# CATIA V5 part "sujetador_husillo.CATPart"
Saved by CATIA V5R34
Part number: sujetador_husillo
Bounding box of the stored display mesh (mm): x -27.5 to 27.5, y -41.721 to 31, z -25 to 60.531
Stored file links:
  C:\Users\Apolinar\Desktop\cnc\sujetador_husillo.CATPart
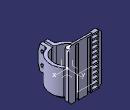
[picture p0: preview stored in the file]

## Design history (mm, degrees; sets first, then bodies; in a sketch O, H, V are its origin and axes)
AxisSystem1: origin (0, 0, 0), X (1, 0, 0), Y (0, 1, 0), Z (0, 0, 1)
Body1 (main body)
  Sketch1 on XY plane of AxisSystem1, origin (0, 0, 0), H (1, 0, 0), V (0, 1, 0)
    arc A1 centre (0, 0) radius 22.5 from (0, 22.5) to (-1.5, -22.4499) ccw
    arc A2 centre (0, 0) radius 27.5 from (0, 27.5) to (-6.5, -26.7208) ccw
    point P1 (-1.5, -22.4499)
    line L1 (-1.5, -22.4499) -> (-1.5, -28.4355)
    point P2 (-1.5, -28.4355)
    point P3 (-6.5, -26.7208)
    line L2 (-6.5, -26.7208) -> (-6.5, -41.7208)
    point P4 (-6.5, -41.7208)
    line L3 (-6.5, -41.7208) -> (-1.5, -41.7208)
    point P5 (-1.5, -41.7208)
    line L4 (-1.5, -41.7208) -> (-1.5, -28.4355)
    axis line L5 (0, 34.1099) -> (0, -44.3897)
    point P6 (0, 34.1099)
    point P7 (0, -44.3897)
    point P8 (0, 22.5)
    point P9 (0, 27.5)
    point P10 (1.5, -22.4499)
    point P11 (1.5, -28.4355)
    point P12 (6.5, -26.7208)
    point P13 (6.5, -41.7208)
    point P14 (1.5, -41.7208)
    point P15 (0, -44.3897)
    line L6 (1.5, -22.4499) -> (1.5, -28.4355)
    line L7 (6.5, -26.7208) -> (6.5, -41.7208)
    line L8 (6.5, -41.7208) -> (1.5, -41.7208)
    line L9 (1.5, -41.7208) -> (1.5, -28.4355)
    point P16 (0, 27.5)
    arc A3 centre (0, 0) radius 27.5 from (0, 27.5) to (6.5, -26.7208) cw
    point P18 (0, 22.5)
    arc A4 centre (0, 0) radius 22.5 from (0, 22.5) to (1.5, -22.4499) cw
    distance A2 A1 = 5
    radius A1 = 22.5
    length L2 = 15
    length L3 = 5
    distance L4 V = 1.5
    vertical: L1 V, L2 V, L4 V, L5 V
    coincidence: P5 L1, P6 V, L5 P8, L5 P9
    horizontal: L3 H
    symmetry: P1 P10 L5, P2 P11 L5, P3 P12 L5, P4 P13 L5, P5 P14 L5, P7 P15 L5, L1 L6 L5, L2 L7 L5, L3 L8 L5, L4 L9 L5, P9 P16 L5, A2 A3 L5, P8 P18 L5, A1 A4 L5
  Pad1: profile Sketch1, direction (0, 0, 1), length 20, mirrored extent
  Sketch2 on face of Pad1 from Sketch1.L7, origin (6.5, 0, 0), H (0, 1, 0), V (0, 0, 1)
    point P1 (-34.2208, 10)
    point P2 (-34.2208, 12.7)
    construction circle A1 centre (-34.2208, 10) radius 3.1177
    construction circle A2 centre (-34.2208, 10) radius 2.7
    point P3 (-32.6619, 12.7)
    point P4 (-35.7796, 12.7)
    point P5 (-37.3385, 10)
    point P6 (-35.7796, 7.3)
    point P7 (-32.6619, 7.3)
    point P8 (-31.1031, 10)
    line L1 (-32.6619, 12.7) -> (-35.7796, 12.7)
    line L2 (-35.7796, 12.7) -> (-37.3385, 10)
    line L3 (-37.3385, 10) -> (-35.7796, 7.3)
    line L4 (-35.7796, 7.3) -> (-32.6619, 7.3)
    line L5 (-32.6619, 7.3) -> (-31.1031, 10)
    line L6 (-31.1031, 10) -> (-32.6619, 12.7)
    construction line L7 (-34.2208, 10) -> (-34.2208, 12.7)
    reference projected line E1 (-41.7208, -20) -> (-41.7208, 20) from edge [face of Pad1 from Sketch1.L7 | face of Pad1 from Sketch1.L8]
    reference projected line E2 (-26.7208, -20) -> (-26.7208, 20) from edge [face of Pad1 from Sketch1.A3 | face of Pad1 from Sketch1.L7]
    reference projected line E3 (-41.7208, -20) -> (-41.7208, 20) from edge [face of Pad1 from Sketch1.L3 | face of Pad1 from Sketch1.L2]
    point P10 (-34.2208, -12.7)
    construction circle A3 centre (-34.2208, -10) radius 3.1177
    construction circle A4 centre (-34.2208, -10) radius 2.7
    point P11 (-32.6619, -12.7)
    point P12 (-35.7796, -12.7)
    point P13 (-37.3385, -10)
    point P14 (-35.7796, -7.3)
    point P15 (-32.6619, -7.3)
    point P16 (-31.1031, -10)
    construction line L8 (-34.2208, -10) -> (-34.2208, -12.7)
    line L9 (-32.6619, -12.7) -> (-35.7796, -12.7)
    line L10 (-35.7796, -12.7) -> (-37.3385, -10)
    line L11 (-37.3385, -10) -> (-35.7796, -7.3)
    line L12 (-35.7796, -7.3) -> (-32.6619, -7.3)
    line L13 (-32.6619, -7.3) -> (-31.1031, -10)
    line L14 (-31.1031, -10) -> (-32.6619, -12.7)
    distance L4 L1 = 5.4
    distance P1 H = 10
    distance E1 E2 = 15 (reference)
    distance E3 P1 = 7.5
    coincidence: A1 P3, A1 P4, A1 P5, A1 P6, A1 P7, A1 P8
    tangency: A2 L1, A2 L2, A2 L3, A2 L4, A2 L5, A2 L6
    midpoint: P2 L1
    vertical: L7 V
    symmetry: P2 P10 H, A1 A3 H, A2 A4 H, P3 P11 H, P4 P12 H, P5 P13 H, P6 P14 H, P7 P15 H, P8 P16 H, L7 L8 H, L1 L9 H, L2 L10 H, L3 L11 H, L4 L12 H, L5 L13 H, L6 L14 H
  Pocket1: profile Sketch2, direction (-1, 0, 0), length 3
  Sketch3 on end face of Pocket1, origin (3.5, 0, 0), H (0, 1, 0), V (0, 0, 1)
    circle A1 centre (-34.2208, 10) radius 1.75
    point P1 (-34.2208, 10)
    reference projected line E1 (-41.7208, -20) -> (-41.7208, 20) from edge [face of Pad1 from Sketch1.L7 | face of Pad1 from Sketch1.L8]
    reference projected line E2 (-41.7208, 20) -> (-26.7208, 20) from edge [face of Pad1 from Sketch1.L7 | end face of Pad1]
    circle A2 centre (-34.2208, -10) radius 1.75
    radius A1 = 1.75
    distance P1 E1 = 7.5
    distance P1 E2 = 10
    symmetry: A1 A2 H
  Pocket2: profile Sketch3, direction (-1, 0, 0), through (limit type 3)
  Sketch4 on start face of Pad1, origin (0, 0, -20), H (1, 0, 0), V (0, -1, 0)
    arc A1 centre (0, 0) radius 9.25 from (-1.5, 9.1276) to (1.5, 9.1276) ccw
    arc A2 centre (0, 0) radius 27.5 from (-1.5, 27.4591) to (1.5, 27.4591) ccw
    reference projected arc E1 centre (0, 0) radius 27.5 from (0, -27.5) to (6.5, 26.7208) ccw from edge [start face of Pad1 | face of Pad1 from Sketch1.A3]
    line L1 (-1.5, 9.1276) -> (-1.5, 27.4591)
    line L2 (1.5, 9.1276) -> (1.5, 27.4591)
    reference projected line E2 (-1.5, 28.4355) -> (-1.5, 22.4499) from edge [start face of Pad1 | face of Pad1 from Sketch1.L1]
    reference projected line E3 (1.5, 22.4499) -> (1.5, 28.4355) from edge [start face of Pad1 | face of Pad1 from Sketch1.L6]
    circle A3 centre (-14.25, 0) radius 2.25
    point P5 (-14.25, 0)
    reference projected arc E4 centre (0, 0) radius 22.5 from (-1.5, 22.4499) to (0, -22.5) ccw from edge [start face of Pad1 | face of Pad1 from Sketch1.A1]
    circle A4 centre (14.25, 0) radius 2.25
    radius A1 = 9.25
    radius A3 = 2.25
    distance A3 E4 = 6
    coincidence: E1 A2, L1 E2, L2 E3, P5 H
    vertical: L1 V, L2 V
    symmetry: A3 A4 V
  Pad2: profile Sketch4, direction (0, 0, -1), length 5
  Chamfer1: length 3, angle 45, on edge [face of Pad2 | end face of Pad2]
  Fillet1: radius 3, on edge [start face of Pad2 | face of Pad1 from Sketch1.A1]
  Plane1: type Offset, RefPlane ZX plane of AxisSystem1, Offset 30
  Sketch5 on Plane1, origin (0, 30, 0), H (-1, 0, 0), V (0, 0, 1)
    point P1 (0, 17.5)
    line L1 (27.5, 60) -> (27.5, -22)
    line L2 (24.5, -25) -> (-24.5, -25)
    line L3 (-27.5, -22) -> (-27.5, 60)
    line L4 (-27.5, 60) -> (27.5, 60)
    reference projected line E1 (24.5, -25) -> (-24.5, -25) from edge [face of Chamfer1 | end face of Pad2]
    point P5 (27.5, -22)
    point P7 (-27.5, -22)
    reference projected line E2 (27.5, -22) -> (-27.5, -22) from edge [face of Pad2 | face of Chamfer1]
    line L5 (-27.5, -22) -> (-27.5, -25)
    point P8 (-27.5, -25)
    line L6 (-27.5, -25) -> (-24.5, -25)
    line L7 (24.5, -25) -> (27.5, -25)
    point P9 (27.5, -25)
    line L8 (27.5, -25) -> (27.5, -22)
    distance V L1 = 27.5
    distance L4 L2 = 85
    coincidence: P1 V, E1 L2, P5 E2, E2 P7, P8 L2, P9 L1
    vertical: L1 V, L3 V, L5 V, L8 V
    horizontal: L2 H, L4 H, L6 H, L7 H
    equidistance: L1 L3 P1, L2 L4 P1
  Pad3: profile Sketch5, direction (0, -1, 0), length 6
  DatumCurve1
  Sketch6 on start face of Pad3, origin (0, 30, 0), H (-1, 0, 0), V (0, 0, 1)
    point P1 (16.5, 17.5)
    line L1 (21.5, 60) -> (21.5, -25)
    line L2 (21.5, -25) -> (11.5, -25)
    line L3 (11.5, -25) -> (11.5, 60)
    line L4 (11.5, 60) -> (21.5, 60)
    reference projected line E1 (27.5, 60) -> (-27.5, 60) from edge [face of Pad3 from Sketch5.L4 | start face of Pad3]
    reference projected line E2 (-24.5, -25) -> (24.5, -25) from edge [face of Pad3 from Sketch5.L2 | start face of Pad3]
    reference projected line E3 (21.5, 55) -> (21.5, 60) from edge of DatumCurve1
    distance L1 L3 = 10
    vertical: L1 V, L3 V
    horizontal: L2 H, L4 H
    equidistance: L1 L3 P1, L2 L4 P1
    coincidence: L4 E1, E2 L2
    tangency: L1 E3
  Pocket3: profile Sketch6, direction (0, -1, 0), length 4
  Sketch7 on face of Pocket3 from Sketch6.L3, origin (-11.5, 0, 0), H (0, -1, 0), V (0, 0, 1)
    point P1 (-26, -25)
    line L1 (-26, -25) -> (-31, -23.6603)
    line L2 (-31, -23.6603) -> (-31, -21.3397)
    line L3 (-31, -21.3397) -> (-26, -20)
    line L4 (-26, -20) -> (-26, -25)
    reference projected line E1 (-26, 60) -> (-26, -25) from edge [end face of Pocket3 | face of Pocket3 from Sketch6.L3]
    reference projected line E2 (-30, -25) -> (-26, -25) from edge [face of Pad3 | face of Pocket3 from Sketch6.L3]
    axis line L5 (-31, -22.5) -> (-26, -22.5)
    point P5 (-31, -22.5)
    point P6 (-26, -22.5)
    construction line L6 (-31, -15.179) -> (-26, -15.179)
    line L7 (-26, -17.679) -> (-31, -16.3393)
    line L8 (-31, -16.3393) -> (-31, -14.0187)
    line L9 (-31, -14.0187) -> (-26, -12.679)
    line L10 (-26, -12.679) -> (-26, -17.679)
    construction line L11 (-31, -7.858) -> (-26, -7.858)
    line L12 (-26, -10.358) -> (-31, -9.0183)
    line L13 (-31, -9.0183) -> (-31, -6.6977)
    line L14 (-31, -6.6977) -> (-26, -5.358)
    line L15 (-26, -5.358) -> (-26, -10.358)
    construction line L16 (-31, -0.537) -> (-26, -0.537)
    line L17 (-26, -3.037) -> (-31, -1.6973)
    line L18 (-31, -1.6973) -> (-31, 0.6233)
    line L19 (-31, 0.6233) -> (-26, 1.963)
    line L20 (-26, 1.963) -> (-26, -3.037)
    construction line L21 (-31, 6.784) -> (-26, 6.784)
    line L22 (-26, 4.284) -> (-31, 5.6237)
    line L23 (-31, 5.6237) -> (-31, 7.9443)
    line L24 (-31, 7.9443) -> (-26, 9.284)
    line L25 (-26, 9.284) -> (-26, 4.284)
    construction line L26 (-31, 14.105) -> (-26, 14.105)
    line L27 (-26, 11.605) -> (-31, 12.9447)
    line L28 (-31, 12.9447) -> (-31, 15.2653)
    line L29 (-31, 15.2653) -> (-26, 16.605)
    line L30 (-26, 16.605) -> (-26, 11.605)
    construction line L31 (-31, 21.426) -> (-26, 21.426)
    line L32 (-26, 18.926) -> (-31, 20.2657)
    line L33 (-31, 20.2657) -> (-31, 22.5863)
    line L34 (-31, 22.5863) -> (-26, 23.926)
    line L35 (-26, 23.926) -> (-26, 18.926)
    construction line L36 (-31, 28.747) -> (-26, 28.747)
    line L37 (-26, 26.247) -> (-31, 27.5867)
    line L38 (-31, 27.5867) -> (-31, 29.9073)
    line L39 (-31, 29.9073) -> (-26, 31.247)
    line L40 (-26, 31.247) -> (-26, 26.247)
    construction line L41 (-31, 36.068) -> (-26, 36.068)
    line L42 (-26, 33.568) -> (-31, 34.9077)
    line L43 (-31, 34.9077) -> (-31, 37.2283)
    line L44 (-31, 37.2283) -> (-26, 38.568)
    line L45 (-26, 38.568) -> (-26, 33.568)
    construction line L46 (-31, 43.389) -> (-26, 43.389)
    line L47 (-26, 40.889) -> (-31, 42.2287)
    line L48 (-31, 42.2287) -> (-31, 44.5493)
    line L49 (-31, 44.5493) -> (-26, 45.889)
    line L50 (-26, 45.889) -> (-26, 40.889)
    construction line L51 (-31, 50.71) -> (-26, 50.71)
    line L52 (-26, 48.21) -> (-31, 49.5497)
    line L53 (-31, 49.5497) -> (-31, 51.8703)
    line L54 (-31, 51.8703) -> (-26, 53.21)
    line L55 (-26, 53.21) -> (-26, 48.21)
    construction line L56 (-31, 58.031) -> (-26, 58.031)
    line L57 (-26, 55.531) -> (-31, 56.8707)
    line L58 (-31, 56.8707) -> (-31, 59.1913)
    line L59 (-31, 59.1913) -> (-26, 60.531)
    line L60 (-26, 60.531) -> (-26, 55.531)
    angle L1 L4 = 75
    distance L2 L4 = 5
    length L4 = 5
    length L2 = 2.3205 (reference)
    vertical: L2 V, L4 V
    coincidence: E1 L4, P1 E2
    horizontal: L5 H
    midpoint: P5 L2, P6 L4
  Pad4: profile Sketch7, direction (-1, 0, 0), length 10
  DatumCurve2 to DatumCurve12
  Sketch8 on face of Pad3 from Sketch5.L4, origin (0, 0, 60), H (1, 0, 0), V (0, 1, 0)
    line L1 (-9.0986, 30) -> (-11.2427, 25.7117)
    line L2 (-11.2427, 25.7117) -> (-1.7573, 25.7117)
    line L3 (-1.7573, 25.7117) -> (-3.9014, 30)
    line L4 (-3.9014, 30) -> (-9.0986, 30)
    reference projected line E1 (-27.5, 30) -> (27.5, 30) from edge [face of Pad3 from Sketch5.L4 | start face of Pad3]
    reference projected line E2 (-9, 29.8617) -> (-11, 25.8617) from edge of DatumCurve2
    reference projected line E3 (-2, 25.8617) -> (-4, 29.8617) from edge of DatumCurve3
    reference projected line E4 (-2, 25.8617) -> (-4, 29.8617) from edge of DatumCurve4
    reference projected line E5 (-9, 29.8617) -> (-11, 25.8617) from edge of DatumCurve5
    reference projected line E6 (-11, 25.8617) -> (-2, 25.8617) from edge of DatumCurve6
    line L5 (11.1514, 30) -> (16.3486, 30)
    line L6 (16.3486, 30) -> (18.4927, 25.7117)
    line L7 (18.4927, 25.7117) -> (9.0073, 25.7117)
    line L8 (9.0073, 25.7117) -> (11.1514, 30)
    reference projected line E7 (11.25, 29.8617) -> (9.25, 25.8617) from edge of DatumCurve7
    reference projected line E8 (18.25, 25.8617) -> (16.25, 29.8617) from edge of DatumCurve8
    reference projected line E9 (18.25, 25.8617) -> (16.25, 29.8617) from edge of DatumCurve9
    reference projected line E10 (11.25, 29.8617) -> (9.25, 25.8617) from edge of DatumCurve10
    reference projected line E11 (9.25, 25.8617) -> (18.25, 25.8617) from edge of DatumCurve12
    distance E4 L3 = 0.15
    distance L1 E5 = 0.15
    distance E6 L2 = 0.15
    distance L6 E9 = 0.15
    distance L8 E10 = 0.15
    distance L7 E11 = 0.15
    horizontal: L2 H, L5 H, L7 H
    coincidence: E1 L4, L5 E1
    parallelism: L1 E2, E3 L3, L8 E7, E8 L6
  Pocket4: profile Sketch8, direction (0, 0, -1), through (limit type 6), opposite side length -3
  Fillet2: radius 5, on edge [face of Pad2 | end face of Pad3]; edge [end face of Pad3 | face of Pad2]
  Chamfer2: length 3, angle 75, on edge [face of Pad1 from Sketch1.L8 | end face of Pad1]; edge [face of Pad1 from Sketch1.L3 | end face of Pad1]; edge [start face of Pad1 | face of Pad1 from Sketch1.L8]; edge [start face of Pad1 | face of Pad1 from Sketch1.L3]
  Fillet3: radius 5, on edge [face of Pad1 from Sketch1.L2 | face of Pad2]; edge [face of Pad2 | face of Pad1 from Sketch1.L7]
  Fillet4: radius 3, on edge [face of Pad1 from Sketch1.A1 | face of Pad1]; edge [face of Pad1 | face of Pad1 from Sketch1.A4]
  Chamfer3: length 5, angle 45, on edge [face of Pad3 from Sketch5.L5 | face of Pad3 from Sketch5.L6]; edge [face of Pad3 from Sketch5.L7 | face of Pad3 from Sketch5.L8]; edge [face of Pad3 from Sketch5.L1 | face of Pad3 from Sketch5.L4]; edge [face of Pad3 from Sketch5.L4 | face of Pad3 from Sketch5.L3]
  Chamfer4: length 3, angle 45, on edge [end face of Pad3 | face of Pad3 from Sketch5.L4]
  Fillet5: radius 5, on edge [end face of Pad1 | end face of Pad3]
